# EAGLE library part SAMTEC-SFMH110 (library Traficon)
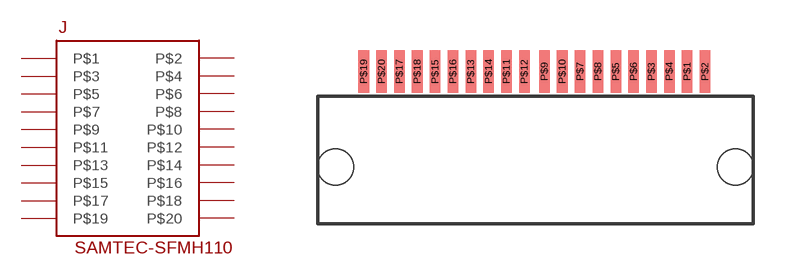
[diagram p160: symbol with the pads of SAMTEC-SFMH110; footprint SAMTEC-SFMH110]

Designator prefix J

## SAMTEC-SFMH110  [SAMTEC-SFMH110]
P$1  P$1
P$2  P$2
P$3  P$3
P$4  P$4
P$5  P$5
P$6  P$6
P$7  P$7
P$8  P$8
P$9  P$9
P$10  P$10
P$11  P$11
P$12  P$12
P$13  P$13
P$14  P$14
P$15  P$15
P$16  P$16
P$17  P$17
P$18  P$18
P$19  P$19
P$20  P$20

## Footprint SAMTEC-SFMH110 (pad centres in mm)
smd 0.38 x 1.52: P$1 5.44,5.46; P$2 6.08,5.46; P$3 4.16,5.46; P$4 4.8,5.46; P$5 2.88,5.46; P$6 3.52,5.46; P$7 1.6,5.46; P$8 2.24,5.46; P$9 0.32,5.46; P$10 0.96,5.46; P$11 -1.04,5.46; P$12 -0.4,5.46; P$13 -2.32,5.46; P$14 -1.68,5.46; P$15 -3.6,5.46; P$16 -2.96,5.46; P$17 -4.88,5.46; P$18 -4.24,5.46; P$19 -6.16,5.46; P$20 -5.52,5.46
hole 1.3 at -7.175,2.03
hole 1.3 at 7.175,2.03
